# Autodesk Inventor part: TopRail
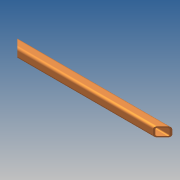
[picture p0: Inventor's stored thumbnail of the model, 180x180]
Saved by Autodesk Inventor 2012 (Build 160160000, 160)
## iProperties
Created: 2007-12
Part Number: TopRail
Document SubType Name: Modeling
Designer: MJ
Material: Aluminum-6061
Stock Number: D-623-012-d
Density: 2.71 g/cm^3
Engineer: MJ
Mass: 2117.04 g
Surface Area: 2489.45 cm^2
Volume: 781.196 cm^3
RuleStatus: InUse
Title: DgPr Assembly Cell
Author: MJ
Comments: 1.50" X 1.50" X 1/8" WALL TUBE X 44 1/8"
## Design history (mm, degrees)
sketch "Sketch2"
  geometry: L1 (-12.7, -25.4)-(12.7, -25.4); L2 (25.4, -12.7)-(25.4, 12.7); L3 (12.7, 25.4)-(-12.7, 25.4); L4 (-25.4, 12.7)-(-25.4, -12.7); L5 (-19.05, 12.7)-(-19.05, -12.7); L6 (-12.7, -19.05)-(12.7, -19.05); L7 (19.05, -12.7)-(19.05, 12.7); L8 (12.7, 19.05)-(-12.7, 19.05); A1 r 12.7 centre (12.7, 12.7) between (25.4, 12.7) and (12.7, 25.4); A2 r 12.7 centre (-12.7, 12.7) between (-12.7, 25.4) and (-25.4, 12.7); A3 r 12.7 centre (-12.7, -12.7) between (-25.4, -12.7) and (-12.7, -25.4); A4 r 12.7 centre (12.7, -12.7) between (12.7, -25.4) and (25.4, -12.7); A5 r 6.35 centre (-12.7, 12.7) between (-12.7, 19.05) and (-19.05, 12.7); A6 r 6.35 centre (-12.7, -12.7) between (-19.05, -12.7) and (-12.7, -19.05); A7 r 6.35 centre (12.7, -12.7) between (12.7, -19.05) and (19.05, -12.7); A8 r 6.35 centre (12.7, 12.7) between (19.05, 12.7) and (12.7, 19.05); 6 further points
  constraints: 16 end point, 16 point on circle, 8 centre point, 8 tangent, 6 point on line, 5 parallel, 3 equal radius, 2 horizontal alignment, 2 midpoint, 2 perpendicular, 2 vertical alignment, 1 horizontal, 8 other
extrude "Extrusion1" new body sketch "Sketch2" taper "d5" = 0 deg
sketch "Sketch3"
  geometry: L1 (25.4, 812.8)-(0, 812.8) reference; L2 (0, 0)-(25.4, 0) reference; L3 (-12.7, 812.8)-(0, 812.8) reference; L4 (25.4, 812.8)-(38.1, 812.8) reference; L5 (-12.7, 812.8)-(-12.7, 0) reference; L6 (38.1, 812.8)-(38.1, 0) reference; L7 (38.1, 0)-(25.4, 0) reference; L8 (0, 0)-(-12.7, 0) reference; L9 (38.1, 0)-(-12.7, 50.8); L10 (38.1, 812.8)-(-12.7, 762); L11 (0, 0)-(0, 812.8) reference; L12 (25.4, 812.8)-(25.4, 0) reference; 1 further point
  constraints: 4 end point, 2 point on line
  dimensions: "TubeEndAngle1" = 45 deg angle of L8 L9; "TubeEndAngle2" = 45 deg angle of L1 L10
extrude "Extrusion2" cut sketch "Sketch3" stored distance "d8" = 25.4; taper "d9" = 0 deg
body "Solid1"
